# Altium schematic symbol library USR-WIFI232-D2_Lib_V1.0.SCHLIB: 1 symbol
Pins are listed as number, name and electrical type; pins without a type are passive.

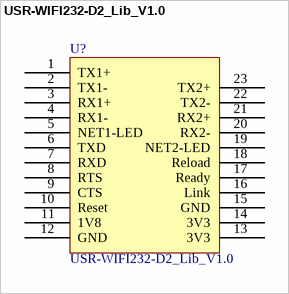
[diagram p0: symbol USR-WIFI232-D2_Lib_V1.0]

## USR-WIFI232-D2_Lib_V1.0
designator U?
footprint USR-D
pins: 1 TX1+, 2 TX1-, 3 RX1+, 4 RX1-, 5 NET1-LED, 6 TXD, 7 RXD, 8 RTS, 9 CTS, 10 Reset, 11 1V8, 12 GND, 13 3V3, 14 3V3, 15 GND, 16 Link, 17 Ready, 18 Reload, 19 NET2-LED, 20 RX2-, 21 RX2+, 22 TX2-, 23 TX2+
